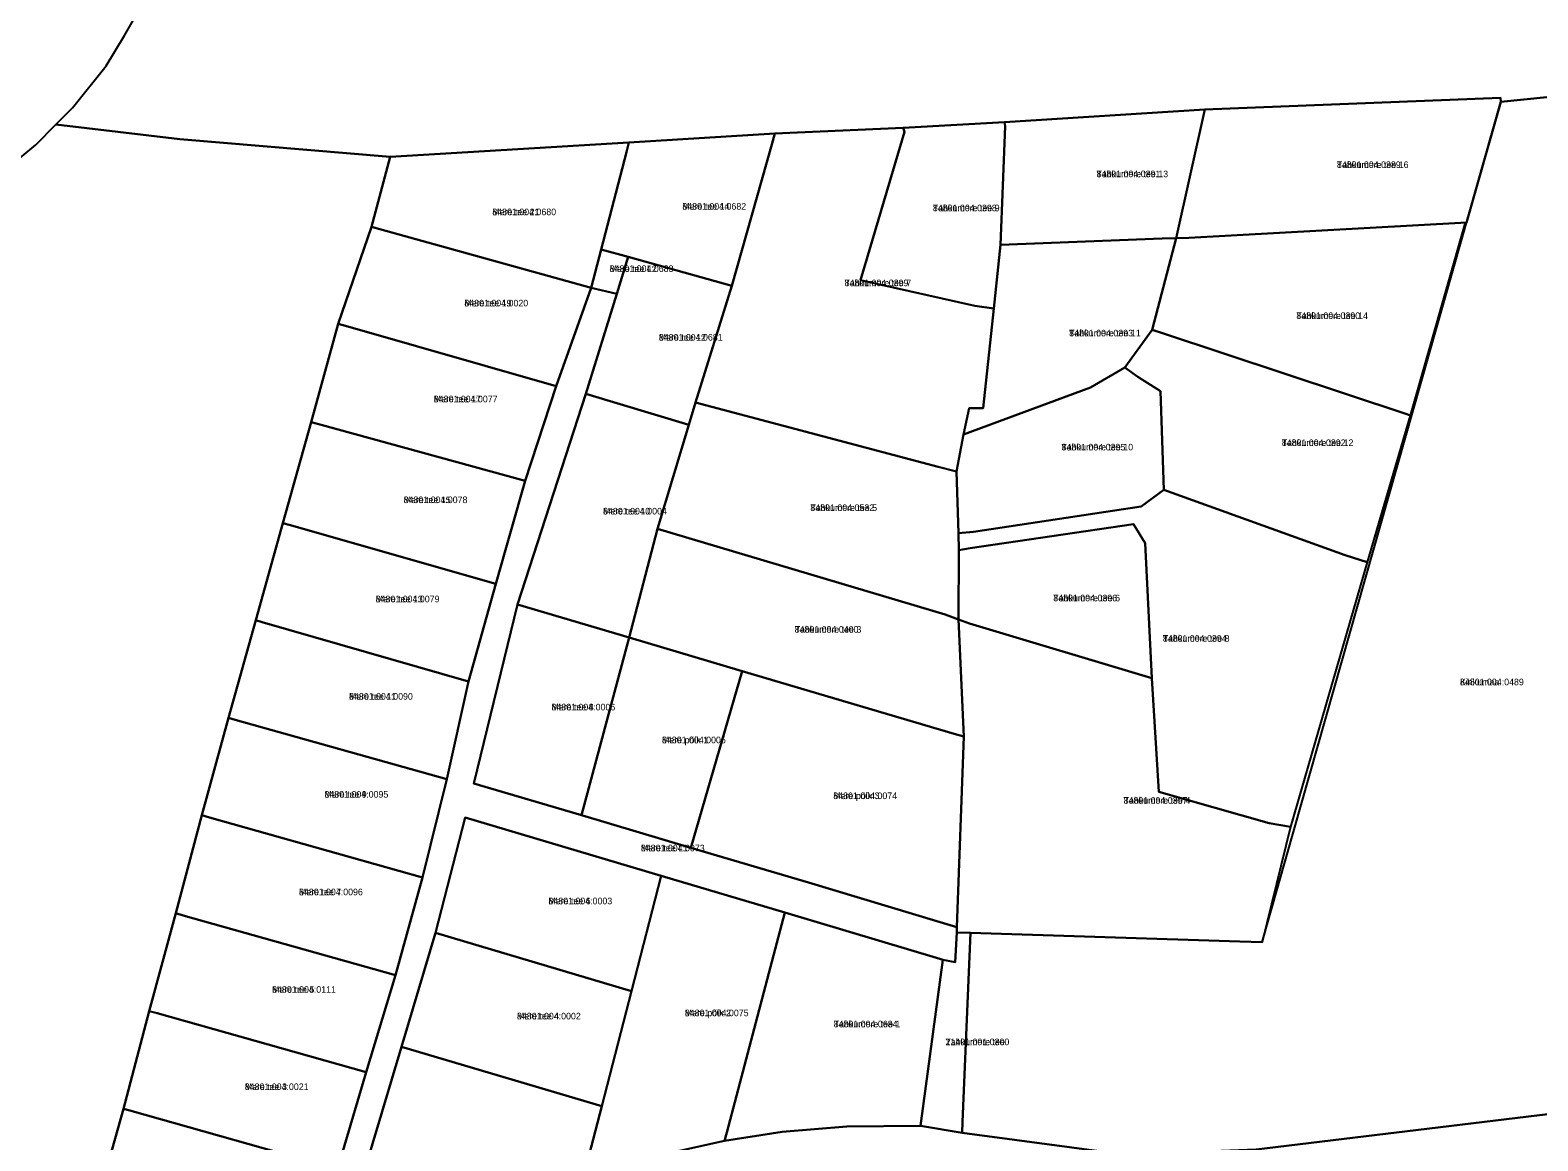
# Model space of a CAD drawing. Extents: x 520985 to 542706, y 6413723 to 6468993.
# Drawn here: x 528345 to 528687.6, y 6456212.7 to 6456465 of the extents above; entities that cross this region are included whole.
import ezdxf

# ---------------------------------------------------------------- set-up
doc = ezdxf.new("R2010")
doc.units = 0
for name, color, linetype in [('L_AADRESS', 7, 'Continuous'), ('PIIR', 7, 'Continuous'), ('TUNNUS', 7, 'Continuous')]:
    doc.layers.add(name, color=color, linetype=linetype)

msp = doc.modelspace()

# ---------------------------------------------------------------- linework, layer by layer
at = {"layer": 'PIIR'}
for points in [[(528737.44, 6456454.64), (528679.22, 6456448.72), (528679.16, 6456449.67), (528611.92, 6456446.99), (528566.41, 6456444.16), (528543.4, 6456442.85), (528514.2, 6456441.56), (528481.04, 6456439.5), (528426.76, 6456436.25), (528378.98, 6456440.23), (528350.84, 6456443.58), (528354.62, 6456447.41), (528362.24, 6456456.93), (528366.38, 6456463.79), (528371.66, 6456473.02)], [(528332.39, 6456427.51), (528346.26, 6456438.94), (528350.84, 6456443.58), (528378.98, 6456440.23), (528426.76, 6456436.25), (528422.57, 6456420.37), (528415, 6456398.29), (528408.84, 6456375.95), (528402.38, 6456353.05), (528396.24, 6456330.97), (528390.05, 6456308.8), (528384.02, 6456286.64), (528378.05, 6456264.38), (528372.01, 6456242.17), (528366.21, 6456219.91), (528362.91, 6456208.35), (528361.65, 6456203.1), (528353.55, 6456174.72), (528353.76, 6456171.88), (528354.63, 6456170.34), (528352.95, 6456163.36), (528352.62, 6456161.99), (528349.83, 6456160.45), (528325.56, 6456146.03)], [(528414.79, 6456206.25), (528421.37, 6456228.24), (528427.99, 6456250.3), (528434.12, 6456272.49), (528439.68, 6456294.83), (528444.62, 6456317.01), (528450.78, 6456339.2), (528457.51, 6456362.65), (528464.51, 6456384.14), (528472.47, 6456406.47), (528478.27, 6456405.13), (528471.23, 6456382.38), (528455.71, 6456334.56), (528445.81, 6456293.85), (528470.31, 6456286.67), (528495.12, 6456279.24), (528521.84, 6456271.34), (528551.76, 6456262.36), (528555.59, 6456261.21), (528555.56, 6456260.04), (528555.18, 6456253.26), (528552.38, 6456253.81), (528551.72, 6456254.01), (528516.48, 6456264.57), (528488.41, 6456272.88), (528443.85, 6456286.12), (528437.13, 6456259.96), (528429.36, 6456234), (528420.55, 6456204.62)], [(528325.56, 6456146.03), (528349.83, 6456160.45), (528352.62, 6456161.99), (528365.61, 6456167.8), (528371.6, 6456170.12), (528411.61, 6456184.79), (528411.94, 6456186.98), (528420.26, 6456190.35), (528421.58, 6456188.22), (528471.03, 6456205.61), (528502.79, 6456212.71), (528515.88, 6456214.73), (528530.56, 6456215.92), (528547.33, 6456216.05), (528556.78, 6456214.48), (528593.64, 6456209.59), (528623.6, 6456210.72), (528783.08, 6456229.98)]]:
    msp.add_lwpolyline(points, dxfattribs=at)
for points in [[(528556.88, 6456216.98), (528558.68, 6456259.93), (528619.9, 6456257.99), (528624.94, 6456257.83), (528679.22, 6456448.72), (528737.44, 6456454.64), (528782.62, 6456232.25), (528783.08, 6456229.98), (528623.6, 6456210.72), (528593.64, 6456209.59), (528556.78, 6456214.48)], [(528605.42, 6456417.74), (528611.92, 6456446.99), (528679.16, 6456449.67), (528679.22, 6456448.72), (528671.44, 6456421.35), (528670.1, 6456421.27), (528608.34, 6456417.86)], [(528566.6, 6456443.23), (528566.41, 6456444.16), (528611.92, 6456446.99), (528605.42, 6456417.74), (528602.21, 6456417.7), (528565.52, 6456416.26)], [(528474.74, 6456415.22), (528480.47, 6456437.32), (528481.04, 6456439.5), (528514.2, 6456441.56), (528513.5, 6456439.09), (528504.47, 6456406.91), (528480.88, 6456413.51)], [(528513.5, 6456439.09), (528514.2, 6456441.56), (528543.4, 6456442.85), (528543.68, 6456441.91), (528533.69, 6456408.19), (528559.67, 6456402.39), (528563.97, 6456401.77), (528561.55, 6456379.16), (528558.39, 6456379.14), (528557.06, 6456373.16), (528555.52, 6456364.72), (528551.31, 6456365.84), (528496.15, 6456380.42), (528504.47, 6456406.91)], [(528543.68, 6456441.91), (528543.4, 6456442.85), (528566.41, 6456444.16), (528566.6, 6456443.23), (528565.52, 6456416.26), (528563.97, 6456401.77), (528559.67, 6456402.39), (528533.69, 6456408.19)], [(528422.57, 6456420.37), (528426.76, 6456436.25), (528481.04, 6456439.5), (528480.47, 6456437.32), (528474.74, 6456415.22), (528472.47, 6456406.47), (528424.45, 6456419.85)], [(528600, 6456396.94), (528605.42, 6456417.74), (528608.34, 6456417.86), (528670.1, 6456421.27), (528671.08, 6456421.36), (528658.6, 6456377.45), (528657.83, 6456377.76), (528602.29, 6456396.15)], [(528415, 6456398.29), (528422.57, 6456420.37), (528424.45, 6456419.85), (528472.47, 6456406.47), (528464.51, 6456384.14), (528416.63, 6456397.85)], [(528558.39, 6456379.14), (528561.55, 6456379.16), (528563.97, 6456401.77), (528565.52, 6456416.26), (528602.21, 6456417.7), (528605.42, 6456417.74), (528600, 6456396.94), (528593.79, 6456388.38), (528585.95, 6456383.86), (528557.06, 6456373.16)], [(528474.74, 6456415.22), (528480.88, 6456413.51), (528478.27, 6456405.13), (528472.47, 6456406.47)], [(528480.88, 6456413.51), (528504.47, 6456406.91), (528496.15, 6456380.42), (528494.65, 6456375.39), (528471.23, 6456382.38), (528478.27, 6456405.13)], [(528408.84, 6456375.95), (528415, 6456398.29), (528416.63, 6456397.85), (528464.51, 6456384.14), (528457.51, 6456362.65), (528410.29, 6456375.55)], [(528601.9, 6456383), (528596.75, 6456386.27), (528593.79, 6456388.38), (528600, 6456396.94), (528602.29, 6456396.15), (528657.83, 6456377.76), (528658.6, 6456377.45), (528648.85, 6456344.15), (528643.87, 6456345.76), (528602.6, 6456360.61)], [(528555.95, 6456350.71), (528555.52, 6456364.72), (528557.06, 6456373.16), (528585.95, 6456383.86), (528593.79, 6456388.38), (528596.75, 6456386.27), (528601.9, 6456383), (528602.6, 6456360.61), (528597.48, 6456356.78), (528559.35, 6456351.05)], [(528471.23, 6456382.38), (528494.65, 6456375.39), (528487.56, 6456351.7), (528481.08, 6456327.04), (528455.71, 6456334.56)], [(528552.91, 6456332.23), (528487.56, 6456351.7), (528494.65, 6456375.39), (528496.15, 6456380.42), (528551.31, 6456365.84), (528555.52, 6456364.72), (528555.95, 6456350.71), (528556.06, 6456346.89), (528555.93, 6456331.11)], [(528402.38, 6456353.05), (528408.84, 6456375.95), (528410.29, 6456375.55), (528457.51, 6456362.65), (528450.78, 6456339.2), (528403.82, 6456352.64)], [(528599.9, 6456317.76), (528598.37, 6456348.49), (528595.72, 6456352.76), (528558.58, 6456347.34), (528556.06, 6456346.89), (528555.95, 6456350.71), (528559.35, 6456351.05), (528597.48, 6456356.78), (528602.6, 6456360.61), (528643.87, 6456345.76), (528648.85, 6456344.15), (528631.4, 6456284.04), (528626.58, 6456284.87), (528601.5, 6456291.94)], [(528396.24, 6456330.97), (528402.38, 6456353.05), (528403.82, 6456352.64), (528450.78, 6456339.2), (528444.62, 6456317.01), (528397.68, 6456330.55)], [(528555.93, 6456331.11), (528556.06, 6456346.89), (528558.58, 6456347.34), (528595.72, 6456352.76), (528598.37, 6456348.49), (528599.9, 6456317.76), (528558.42, 6456330.24)], [(528481.08, 6456327.04), (528487.56, 6456351.7), (528552.91, 6456332.23), (528555.93, 6456331.11), (528557.19, 6456304.53), (528554.94, 6456305.17), (528506.82, 6456319.42)], [(528455.71, 6456334.56), (528481.08, 6456327.04), (528470.31, 6456286.67), (528445.81, 6456293.85)], [(528390.05, 6456308.8), (528396.24, 6456330.97), (528397.68, 6456330.55), (528444.62, 6456317.01), (528439.68, 6456294.83), (528391.59, 6456308.35)], [(528555.56, 6456260.04), (528555.59, 6456261.21), (528557.19, 6456304.53), (528555.93, 6456331.11), (528558.42, 6456330.24), (528599.9, 6456317.76), (528601.5, 6456291.94), (528626.58, 6456284.87), (528631.4, 6456284.04), (528624.94, 6456257.83), (528619.9, 6456257.99), (528558.68, 6456259.93)], [(528481.08, 6456327.04), (528506.82, 6456319.42), (528495.12, 6456279.24), (528470.31, 6456286.67)], [(528495.12, 6456279.24), (528506.82, 6456319.42), (528554.94, 6456305.17), (528557.19, 6456304.53), (528555.59, 6456261.21), (528551.76, 6456262.36), (528521.84, 6456271.34)], [(528384.02, 6456286.64), (528390.05, 6456308.8), (528391.59, 6456308.35), (528439.68, 6456294.83), (528434.12, 6456272.49), (528385.7, 6456286.15)], [(528378.05, 6456264.38), (528384.02, 6456286.64), (528385.7, 6456286.15), (528434.12, 6456272.49), (528427.99, 6456250.3), (528379.74, 6456263.9)], [(528443.85, 6456286.12), (528488.41, 6456272.88), (528481.64, 6456246.71), (528437.13, 6456259.96)], [(528516.48, 6456264.57), (528503.27, 6456214.54), (528502.79, 6456212.71), (528471.03, 6456205.61), (528471.51, 6456207.45), (528474.91, 6456220.55), (528481.64, 6456246.71), (528488.41, 6456272.88)], [(528372.01, 6456242.17), (528378.05, 6456264.38), (528379.74, 6456263.9), (528427.99, 6456250.3), (528421.37, 6456228.24), (528373.83, 6456241.69)], [(528516.48, 6456264.57), (528551.72, 6456254.01), (528552.38, 6456253.81), (528547.33, 6456216.05), (528530.56, 6456215.92), (528515.88, 6456214.73), (528502.79, 6456212.71), (528503.27, 6456214.54)], [(528437.13, 6456259.96), (528481.64, 6456246.71), (528474.91, 6456220.55), (528429.36, 6456234)], [(528558.68, 6456259.93), (528556.88, 6456216.98), (528556.78, 6456214.48), (528547.33, 6456216.05), (528552.38, 6456253.81), (528555.18, 6456253.26), (528555.56, 6456260.04)], [(528366.21, 6456219.91), (528372.01, 6456242.17), (528373.83, 6456241.69), (528421.37, 6456228.24), (528414.79, 6456206.25), (528367.66, 6456219.53)], [(528474.91, 6456220.55), (528471.51, 6456207.45), (528471.03, 6456205.61), (528421.58, 6456188.22), (528420.26, 6456190.35), (528420.55, 6456204.62), (528429.36, 6456234)], [(528367.66, 6456219.53), (528414.79, 6456206.25), (528411.94, 6456186.98), (528411.61, 6456184.79), (528371.6, 6456170.12), (528365.61, 6456167.8), (528362.48, 6456167.65), (528359.04, 6456168.19), (528356.38, 6456169.07), (528354.63, 6456170.34), (528353.76, 6456171.88), (528353.55, 6456174.72), (528361.65, 6456203.1), (528362.91, 6456208.35), (528366.21, 6456219.91)]]:
    msp.add_lwpolyline(points, close=True, dxfattribs=at)

# ---------------------------------------------------------------- texts
at = {"layer": 'L_AADRESS'}
for s, p in [('Tahkumere tee 16', (528641.96, 6456433.71)), ('Tahkumere tee 13', (528587.32, 6456431.62)), ('Mere tee 21', (528450.01, 6456422.99)), ('Mere tee 14', (528493.2, 6456424.24)), ('Tahkumere tee 9', (528550.14, 6456423.88)), ('Mere tee L2', (528476.68, 6456410.09)), ('Tahkumere tee 7', (528530.06, 6456406.86)), ('Mere tee 19', (528443.66, 6456402.26)), ('Tahkumere tee 14', (528632.74, 6456399.4)), ('Tahkumere tee 11', (528581.11, 6456395.45)), ('Mere tee 12', (528487.85, 6456394.49)), ('Mere tee 17', (528436.7, 6456380.47)), ('Tahkumere tee 10', (528579.36, 6456369.54)), ('Tahkumere tee 12', (528629.43, 6456370.54)), ('Mere tee 15', (528429.85, 6456357.57)), ('Mere tee 10', (528475.18, 6456354.99)), ('Tahkumere tee 5', (528522.29, 6456355.77)), ('Mere tee 13', (528423.5, 6456335.03)), ('Tahkumere tee 6', (528577.5, 6456335.26)), ('Tahkumere tee 3', (528518.72, 6456328.12)), ('Tahkumere tee 8', (528602.4, 6456326.07)), ('Kirikumaa', (528669.93, 6456316.18)), ('Mere tee 11', (528417.45, 6456312.9)), ('Mere tee 8', (528463.45, 6456310.47)), ('Mere põik 1', (528488.57, 6456303.01)), ('Mere tee 9', (528411.87, 6456290.65)), ('Mere põik 3', (528527.5, 6456290.32)), ('Tahkumere tee 4', (528593.48, 6456289.26)), ('Mere tee L1', (528483.77, 6456278.45)), ('Mere tee 7', (528406.08, 6456268.47)), ('Mere tee 6', (528462.76, 6456266.42)), ('Mere tee 5', (528399.96, 6456246.31)), ('Mere tee 4', (528455.61, 6456240.26)), ('Mere põik 2', (528493.75, 6456240.99)), ('Tahkumere tee 1', (528527.59, 6456238.46)), ('Tahkumere tee', (528553, 6456234.4)), ('Mere tee 3', (528393.75, 6456224.21))]:
    msp.add_text(s, height=1.5, dxfattribs=at).set_placement(p)
at = {"layer": 'TUNNUS'}
for s, p in [('84801:004:0389', (528641.96, 6456433.71)), ('84801:004:0391', (528587.32, 6456431.62)), ('84801:004:0680', (528450.01, 6456422.99)), ('84801:004:0682', (528493.2, 6456424.24)), ('84801:004:0398', (528550.14, 6456423.88)), ('84801:004:0683', (528476.68, 6456410.09)), ('84801:004:0399', (528530.06, 6456406.86)), ('84801:004:0020', (528443.66, 6456402.26)), ('84801:004:0390', (528632.74, 6456399.4)), ('84801:004:0393', (528581.11, 6456395.45)), ('84801:004:0681', (528487.85, 6456394.49)), ('84801:004:0077', (528436.7, 6456380.47)), ('84801:004:0395', (528579.36, 6456369.54)), ('84801:004:0392', (528629.43, 6456370.54)), ('84801:004:0078', (528429.85, 6456357.57)), ('84801:004:0004', (528475.18, 6456354.99)), ('84801:004:0532', (528522.29, 6456355.77)), ('84801:004:0079', (528423.5, 6456335.03)), ('84801:004:0396', (528577.5, 6456335.26)), ('84801:004:0400', (528518.72, 6456328.12)), ('84801:004:0394', (528602.4, 6456326.07)), ('84801:004:0489', (528669.93, 6456316.18)), ('84801:004:0090', (528417.45, 6456312.9)), ('84801:004:0006', (528463.45, 6456310.47)), ('84801:004:0005', (528488.57, 6456303.01)), ('84801:004:0095', (528411.87, 6456290.65)), ('84801:004:0074', (528527.5, 6456290.32)), ('84801:004:0397', (528593.48, 6456289.26)), ('84801:004:0073', (528483.77, 6456278.45)), ('84801:004:0096', (528406.08, 6456268.47)), ('84801:004:0003', (528462.76, 6456266.42)), ('84801:004:0111', (528399.96, 6456246.31)), ('84801:004:0002', (528455.61, 6456240.26)), ('84801:004:0075', (528493.75, 6456240.99)), ('84801:004:0684', (528527.59, 6456238.46)), ('21401:001:0300', (528553, 6456234.4)), ('84801:004:0021', (528393.75, 6456224.21))]:
    msp.add_text(s, height=1.5, dxfattribs=at).set_placement(p)

doc.saveas('drawing.dxf')
